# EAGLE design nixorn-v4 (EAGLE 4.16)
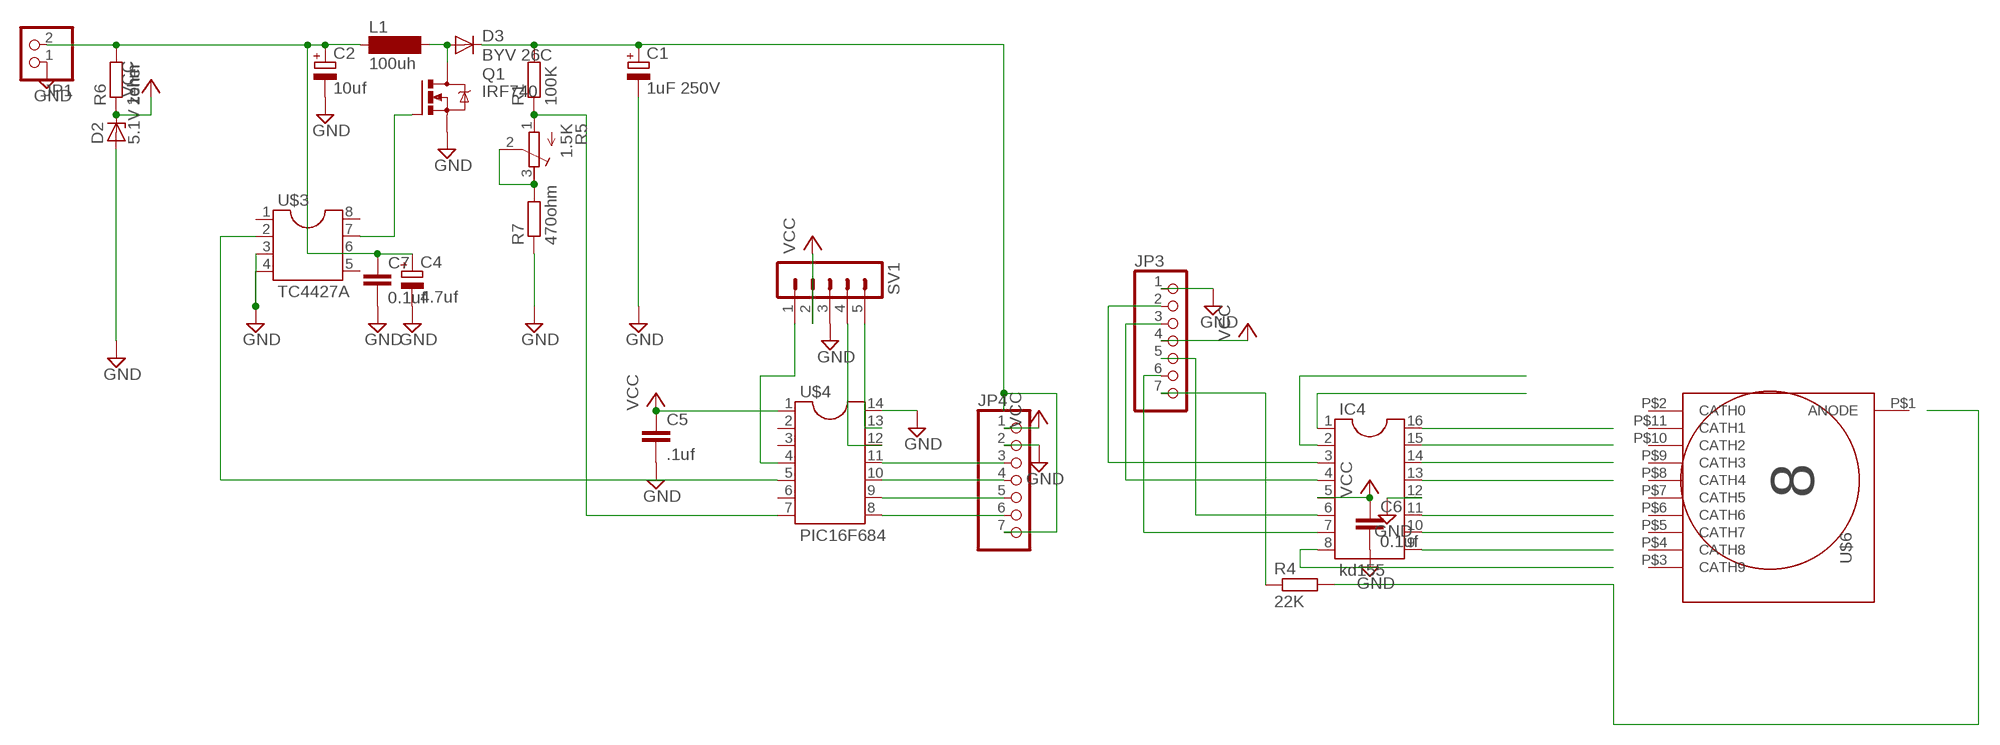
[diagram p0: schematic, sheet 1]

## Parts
C1  1uF 250V  CPOL-EUE2.5-6  [E2,5-6]
C2  10uf  CPOL-EUE2.5-6  [E2,5-6]
C4  4.7uf  CPOL-EUE2.5-6  [E2,5-6]
C5  .1uf  C-EUC0805  [C0805]
C6  0.1uf  C-EUC0805  [C0805]
C7  0.1uf  C-EUC0805  [C0805]
D2  5.1V zener  ZENER-DIODEDO34-7  [DO34Z7]
D3  BYV 26C  DIODE-SM  [DO-SM]
IC4  kd155  DIL16S  [SOCKED-16]
JP1  PINHD-1X2  [1X02]
JP3  PINHD-1X7  [1X07]
JP4  PINHD-1X7  [1X07]
L1  100uh  BS11  [BS11]
Q1  IRF740  [TO220BV]
R1  100K  R-EU_M1206  [M1206]
R4  22K  R-EU_0204/7  [0204/7]
R5  1.5K  R-TRIMM3339P  [RTRIM3339P]
R6  1ohm  R-EU_0204/7  [0204/7]
R7  470ohm  R-EU_0204/7  [0204/7]
SV1  MA05-1  [MA05-1]
U$1  IN12SOCKET  [IN12SOCKET]
U$3  TC4427A  SO-8-150  [SO-8-150]
U$4  PIC16F684  SO-14-150  [SO-14-150]
U$6  NIXIE4822SOCKETPADS  [OVAL14]

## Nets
GND: C1.- C2.- C4.- C5.2 C6.2 C7.2 D2.A IC4.12 JP1.1 JP3.1 JP4.2 Q1.S R7.1 SV1.3 U$3.3 U$3.4 U$4.14
N$1: D3.A L1.2 Q1.D
N$3: U$3.2 U$4.5
N$4: R1.1 R5.1(E) U$4.7
N$6: Q1.G U$3.7
N$7: IC4.8
N$8: R4.2
N$9: IC4.14
N$10: JP3.7 R4.1
N$11: IC4.15
N$12: SV1.1 U$4.4
N$13: IC4.16
N$14: IC4.7 JP3.6
N$15: IC4.6 JP3.5
N$16: SV1.4 U$4.12
N$17: SV1.5 U$4.13
N$18: IC4.9
N$19: IC4.2
N$20: JP4.3 U$4.11
N$21: R5.2(S) R5.3(A) R7.2
N$22: IC4.3 JP3.2
N$23: IC4.4 JP3.3
N$25: JP4.5 U$4.9
N$26: JP4.4 U$4.10
N$27: C1.+ D3.C JP4.7 R1.2
N$28: IC4.1
N$29: JP4.6 U$4.8
N$31: C2.+ C4.+ C7.1 JP1.2 L1.1 R6.2 U$3.6
N$34: IC4.13
N$35: IC4.11
N$36: IC4.10
VCC: C5.1 C6.1 D2.C IC4.5 JP3.4 JP4.1 R6.1 SV1.2 U$4.1
Unconnected: U$3.1 U$3.5 U$3.8 U$4.2 U$4.3 U$4.6 U$6.P$1(ANODE) U$6.P$2(CATH0) U$6.P$3(CATH9) U$6.P$4(CATH8) U$6.P$5(CATH7) U$6.P$6(CATH6) U$6.P$7(CATH5) U$6.P$8(CATH4) U$6.P$9(CATH3) U$6.P$10(CATH2) U$6.P$11(CATH1)

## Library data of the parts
C1 C2 C4 = rcl:CPOL-EU: POLARIZED CAPACITOR, European symbol
C5-C7 = rcl:C-EU: CAPACITOR, European symbol
D2 = diode:ZENER-DIODE: Z-Diode
D3 = nixi-orn-custom:DIODE-SM
IC4 = ic-package:DIL16: Dual In Line
JP1 = pinhead:PINHD-1X2: PIN HEADER
JP3 JP4 = pinhead:PINHD-1X7: PIN HEADER
L1 = inductor-neosid:BS: INDUCTOR
Q1 = transistor-power:IRF740: N-CHANNEL MOS FET
R1 R4 R6 R7 = rcl:R-EU_: RESISTOR, European symbol
R5 = rcl:R-TRIMM: Trimm resistor
SV1 = con-lstb:MA05-1: PIN HEADER
U$1 = nixi-orn-custom:IN12SOCKET
U$3 = SO-pads:SO-8-150
U$4 = SO-pads:SO-14-150
U$6 = nixie:NIXIE4822

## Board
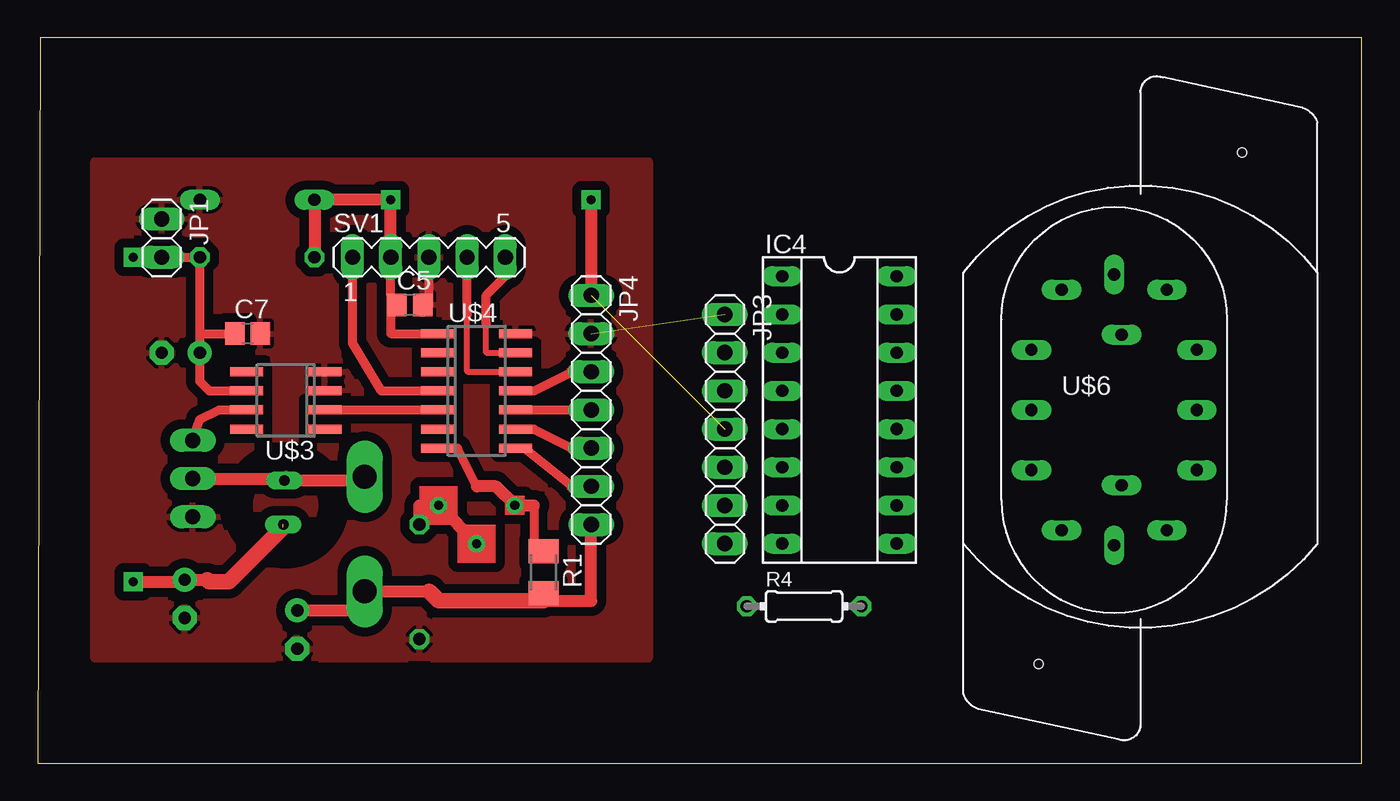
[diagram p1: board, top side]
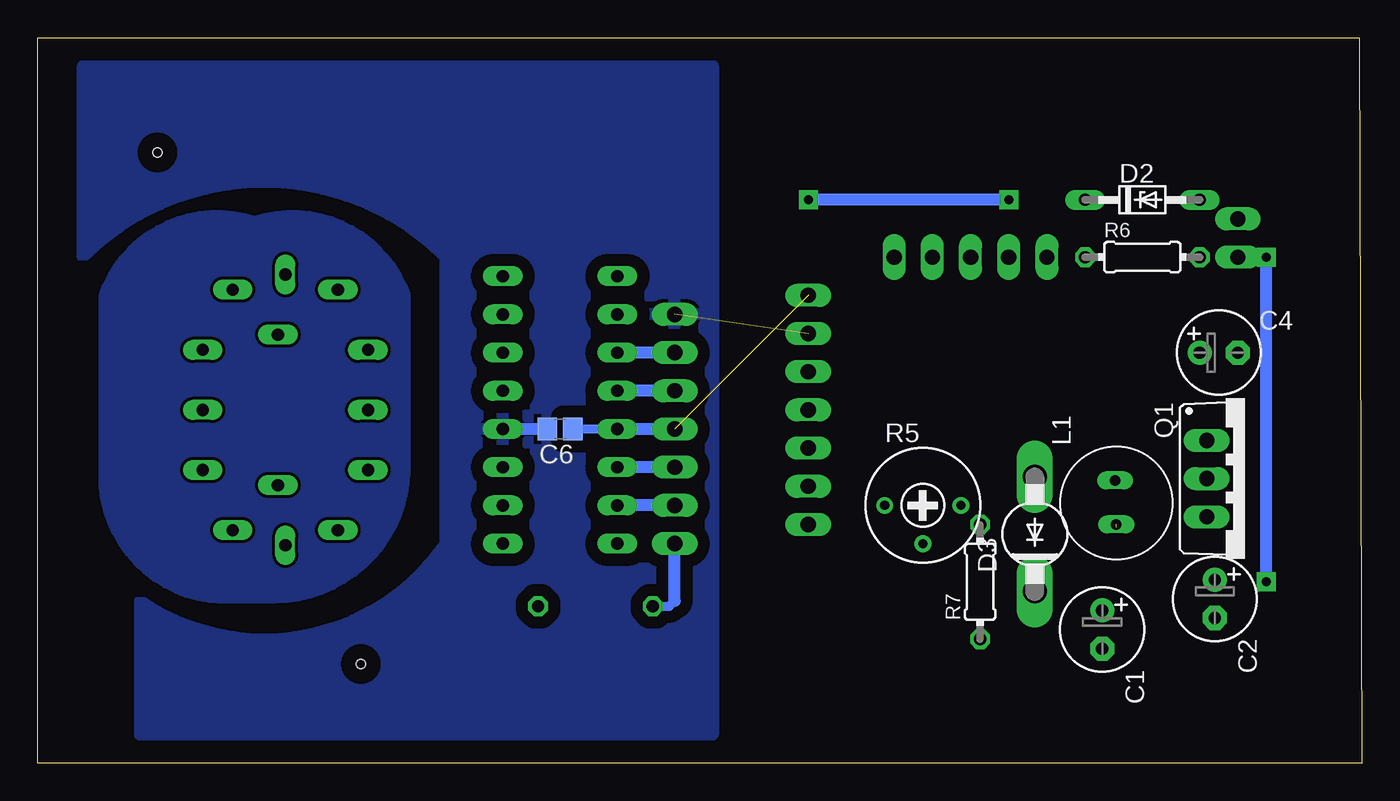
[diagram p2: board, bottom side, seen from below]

Size 88.1 x 48.25 mm. Coordinates in mm from the lower left corner, seen from the top.
Outline: 0,0 88.1,0 88.1,48.25 0.17,48.25 0,0
Copper layers (1*16): Top 0.035mm / dielectric 1.5mm / Bottom 0.035mm
Design rules "default": minimum track width 10mil, minimum drill 24mil, track to track 8mil, track to pad 8mil, pad to pad 8mil, via to via 8mil, smd to smd 8mil, copper to edge 40mil, drill to drill 8mil, minimum pad ring 10mil, minimum via ring 8mil, stop-mask expansion 4mil, vias tented up to drill 0mil, thermal gap 10mil
tRestrict: area 13.3,14 to 19.7,20.3
bRestrict: area 34.3,32.4 to 39.4,37.5

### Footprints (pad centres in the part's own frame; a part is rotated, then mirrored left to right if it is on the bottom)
E2,5-6 = drill 0.813 pad 1.6 round: + -1.27,0 | drill 0.813 pad 1.6 octagon: - 1.27,0
C0805 = smd 1.3 x 1.5: 1 -0.85,0; 2 0.85,0
DO34Z7 = drill 0.813 long: A 3.81,0; C -3.81,0
DO-SM = drill 1.6 long: A 3.81,0; C -3.81,0
SOCKED-16 = drill 0.813 long: 1 -8.89,-3.81; 2 -6.35,-3.81; 3 -3.81,-3.81; 4 -1.27,-3.81; 5 1.27,-3.81; 6 3.81,-3.81; 7 6.35,-3.81; 8 8.89,-3.81; 9 8.89,3.81; 10 6.35,3.81; 11 3.81,3.81; 12 1.27,3.81; 13 -1.27,3.81; 14 -3.81,3.81; 15 -6.35,3.81; 16 -8.89,3.81
1X02 = drill 1.016 long: 1 -1.27,0; 2 1.27,0
1X07 = drill 1.016 long: 1 -7.62,0; 2 -5.08,0; 3 -2.54,0; 4 0,0; 5 2.54,0; 6 5.08,0; 7 7.62,0
BS11 = drill 0.7 long: 1 -1.415,0; 2 1.502,0.087
TO220BV = drill 1.016 long: D 0,-2.54; G -2.54,-2.54; S 2.54,-2.54
M1206 = smd 1.6 x 2: 1 -1.4,0; 2 1.4,0
0204/7 = drill 0.813 octagon: 1 -3.81,0; 2 3.81,0
RTRIM3339P = drill 0.61 round: 1 -2.54,0; 2 0,-2.54; 3 2.54,0
MA05-1 = drill 1.016 long: 1 -5.08,0; 2 -2.54,0; 3 0,0; 4 2.54,0; 5 5.08,0
IN12SOCKET = hole 0.6: 18.54,26; 5,-8
SO-8-150 = smd 0.6 x 2.2: 1 -1.905,-2.6; 2 -0.635,-2.6; 3 0.635,-2.6; 4 1.905,-2.6; 5 1.905,2.6; 6 0.635,2.6; 7 -0.635,2.6; 8 -1.905,2.6
SO-14-150 = smd 0.6 x 2.2: 1 -3.81,-2.6; 2 -2.54,-2.6; 3 -1.27,-2.6; 4 0,-2.6; 5 1.27,-2.6; 6 2.54,-2.6; 7 3.81,-2.6; 8 3.81,2.6; 9 2.54,2.6; 10 1.27,2.6; 11 0,2.6; 12 -1.27,2.6; 13 -2.54,2.6; 14 -3.81,2.6
OVAL14 = drill 0.813 long: P$1 4,-8; P$2 6,-4; P$3 6,0; P$4 6,4; P$5 4,8; P$6 0.5,9; P$7 -3,8; P$8 -5,4; P$9 -5,0; P$10 -5,-4; P$11 -3,-8; P$12 0.5,-9; P$13 1,-5; P$14 1,5

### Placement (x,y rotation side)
C1  17.28,8.89 270 bottom
C2  9.78,10.93 270 bottom
C4  9.53,27.3 0 bottom
C5  24.77,30.48 0 top
C6  53.34,22.23 180 bottom
C7  13.97,28.57 0 top
D2  14.61,37.47 0 bottom
D3  21.76,15.24 90 bottom
IC4  53.34,23.5 270 top
JP1  8.25,34.92 270 top
JP3  45.72,22.23 270 top
JP4  36.83,23.5 270 top
L1  16.34,17.3 90 bottom
Q1  7.79,18.93 270 bottom
R1  33.66,12.7 270 top
R4  50.99,10.44 0 top
R5  29.21,17.14 0 bottom
R6  14.61,33.66 0 bottom
R7  25.4,12.06 90 bottom
SV1  26.04,33.66 0 top
U$1  61.59,14.61 0 top
U$3  16.51,24.13 90 top
U$4  29.21,24.77 270 top
U$6  71.12,23.5 0 top

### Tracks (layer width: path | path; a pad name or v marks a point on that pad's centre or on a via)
GND  (1 unrouted)
  Top 0.61: C5.2 26.04,30.48 SV1.3
  Bottom 0.813: C6.2 IC4.12
  pour Top (isolate 0.813): 3.81,40 40.64,40 40.64,6.98 3.81,6.98
  pour Bottom (isolate 0.813): 43.18,46.36 43.18,1.9 81.28,1.9 81.28,10.79 arc-90 60.96,14.61 60.96,33.66 arc-90 85.09,33.66 85.09,46.36
N$1
  Top 0.813: 16.51,18.93 16.51,18.8 | 16.51,18.8 L1.2 | Q1.D 16.51,18.93 | 16.51,18.93 16.51,19.05 | 16.51,18.8 21.59,18.8 | 21.59,18.8 21.59,18.41 | D3.A 21.59,19.05 21.59,18.8
N$2
  pour Top (isolate 0.61): 3.81,40 40.64,40 40.64,6.98 3.81,6.98
N$3
  Top 0.61: 19.05,23.5 U$3.2 U$4.5
N$4
  Top 0.61: R1.1 33.02,14.1 33.02,17.14 | 29.21,18.41 27.94,20.95 U$4.7
  Top 0.813: 29.21,18.41 30.48,18.41 R5.1 33.02,17.14
N$5
  pour Bottom: 63.5,31.11 63.5,19.69 arc90 72.39,10.79 74.93,10.79 arc90 83.82,18.41 83.82,31.11 arc90 73.66,36.2 arc90
N$6
  Top 0.61: U$3.7 12.07,23.5 10.8,22.86 10.28,21.47 10.16,21.47 | Q1.G 10.16,21.47 | 10.16,21.47 10.16,21.59
N$10
  Bottom 0.61: R4.1 46.08,10.44 45.72,10.79
  Bottom 0.813: 45.72,10.79 JP3.7
N$12
  Top 0.61: 26.67,24.77 U$4.4 22.86,24.77 20.95,27.94 SV1.1
N$14
  Bottom 0.813: JP3.6 IC4.7
N$15
  Bottom 0.813: JP3.5 IC4.6
N$16
  Top 0.406: 28.57,29.84 28.57,26.04 U$4.12
  Top 0.61: 28.57,29.84 SV1.4
N$17
  Top 0.406: 29.84,29.21 29.84,27.3 U$4.13
  Top 0.61: 29.84,29.21 29.84,31.11 31.11,32.39 SV1.5
N$20
  Top 0.61: U$4.11 33.02,24.77 35.56,26.04
  Top 0.813: 35.56,26.04 JP4.3
N$21
  Top 0.813: R5.2 R5.3 25.4,17.14 R7.2
N$22
  Bottom 0.813: JP3.2 IC4.3
N$23
  Bottom 0.813: JP3.3 IC4.4
N$25
  Top 0.61: U$4.9 33.02,22.23 35.56,20.95
  Top 0.813: 35.56,20.95 JP4.5
N$26
  Top 0.61: 31.75,23.5 U$4.10 JP4.4
N$27
  Top 0.813: 33.66,11.43 R1.2 33.66,10.79 36.83,10.79 JP4.7 | C1.+ 21.59,10.16 21.59,11.43 D3.C 26.04,11.43
  Top 1.016: 26.04,11.43 26.67,10.79 33.66,10.79
N$29
  Top 0.61: 35.56,18.41 32.38,20.95 U$4.8
  Top 0.813: 35.56,18.41 JP4.6
N$31  (via drill 0.6 pad 1.27)  (1 unrouted)
  Top 0.61: 11.43,24.77 11.01,25.18 | 13.97,24.77 U$3.6 11.43,24.77 | 10.8,28.57 C7.1 | 11.43,24.77 10.8,25.4 C4.+ 10.8,28.57 | R6.2 10.8,28.57 | R6.2 JP1.2 R6.2
  Top 0.813: v6.35,12.06 10.16,12.06 10.16,12.2 C2.+ 11.43,12.2 11.43,12.06
  Top 1.016: 16.34,15.71 12.7,12.06 11.43,12.06 11.3,12.2 | v6.35,33.66 JP1.2
  Bottom 0.813: v6.35,12.06 v6.35,33.66
VCC  (via drill 0.6 pad 1.27)  (1 unrouted)
  Top 0.61: 23.49,31.11 SV1.2 | 23.49,31.11 23.49,28.57 U$4.1 | C5.1 23.49,31.11 | 19.05,37.47 D2.C
  Top 0.813: D2.C R6.1 | SV1.2 v23.49,37.47 19.05,37.47 | v36.83,37.47 JP4.1
  Bottom 0.61: IC4.5 C6.1
  Bottom 0.813: v23.49,37.47 v36.83,37.47 | JP3.4 IC4.5
(copper drawn outside any net)
  shapes: Top area x3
